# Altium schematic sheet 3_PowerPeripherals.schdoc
size 309 x 223 mm; Symbol: Artery_A4; Device: Artery_A4; Company: Artery Technology; Drawed: SD; Version: 1.3; Page Size: A4; @Project Name: AT-START-A403A V1.3; @Page Count: 5; @Update Date: 2023-11-22; @Create Date: 2022-12-01; @Schematic Name: AT_START_A403A; @Page No: 3; @Page Name: PowerPeripherals
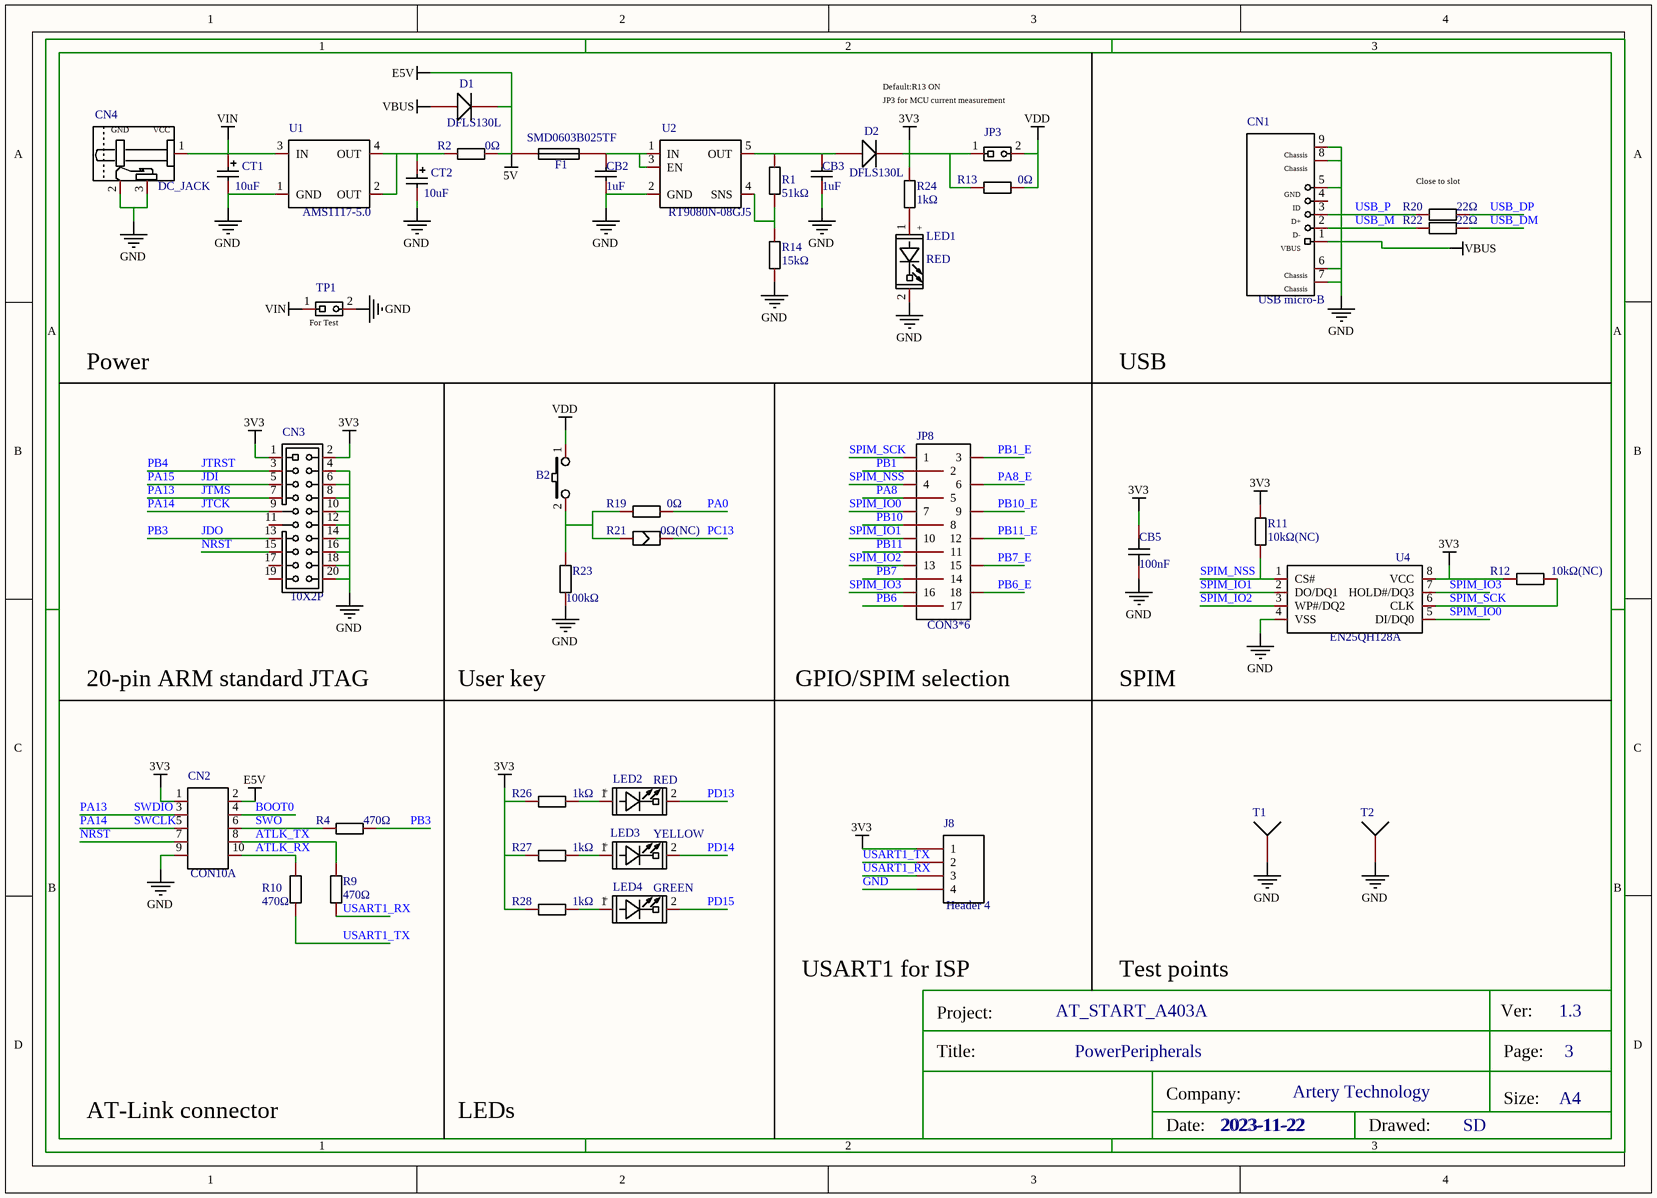
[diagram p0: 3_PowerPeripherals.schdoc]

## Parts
B2  PB,Blue,SMD_2P  [KEY_SOP_6*6]  (value not drawn)
CB2  value 1uF  [C0603]  (hidden comment: CL10A105KB8NNNC)
CB3  value 1uF  [C0603]  (hidden comment: CL10A105KB8NNNC)
CB5  value 100nF  [C0603]  (hidden comment: CC0603KRX7R9BB104)
CN1  USB micro-B  [USB_MIC_DIP]
CN2  CON10A  [HDR2X5]
CN3  10X2P  [JTAG_20]
CN4  DC_JACK  [DC10B]
CT1  value 10uF  [CAP-SMD_L3.5-W2.8-R-RD]  (hidden comment: CA45-B025K106T)
CT2  value 10uF  [CAP-SMD_L3.5-W2.8-R-RD]  (hidden comment: CA45-B025K106T)
D1  DFLS130L  [SOD-123]
D2  DFLS130L  [SOD-123]
F1  SMD0603B025TF  [R0603]
J8  Header 4  [HDR1X4]
JP3  1X2P_2.54M  [HDR1X2]  (value not drawn)
JP8  CON3*6  [HDR3X6]
LED1  RED  [LED0603]
LED2  RED  [LED0603]
LED3  YELLOW  [LED0603]
LED4  GREEN  [LED0603]
R1  value 51kΩ  [R0603]  (hidden comment: 0603WAF5102T5E)
R2  value 0Ω  [R0603]  (hidden comment: 0603WAF0000T5E)
R4  value 470Ω  [R0603]  (hidden comment: 0603WAF4700T5E)
R9  value 470Ω  [R0603]  (hidden comment: 0603WAF4700T5E)
R10  value 470Ω  [R0603]  (hidden comment: 0603WAF4700T5E)
R11  value 10kΩ(NC)  [R0603]  (hidden comment: 0603WAF1002T5E)
R12  value 10kΩ(NC)  [R0603]  (hidden comment: 0603WAF1002T5E)
R13  value 0Ω  [R0603]  (hidden comment: 0603WAF0000T5E)
R14  value 15kΩ  [R0603]  (hidden comment: 0603WAF1502T5E)
R19  value 0Ω  [R0603]  (hidden comment: 0603WAF0000T5E)
R20  value 22Ω  [R0603]  (hidden comment: 0603WAF220JT5E)
R21  value 0Ω(NC)  [SB-PAD]  (hidden comment: NC)
R22  value 22Ω  [R0603]  (hidden comment: 0603WAF220JT5E)
R23  value 100kΩ  [R0603]  (hidden comment: 0603WAF1003T5E)
R24  value 1kΩ  [R0603]  (hidden comment: 0603WAF1001T5E)
R26  value 1kΩ  [R0603]  (hidden comment: 0603WAF1001T5E)
R27  value 1kΩ  [R0603]  (hidden comment: 0603WAF1001T5E)
R28  value 1kΩ  [R0603]  (hidden comment: 0603WAF1001T5E)
T1  Socket  [TestPoint]  (value not drawn)
T2  Socket  [TestPoint]  (value not drawn)
TP1  1X2P_2.54M  [HDR1X2]  (value not drawn)
U1  AMS1117-5.0  [SOT223]
U2  RT9080N-08GJ5  [SOT-23-5]
U4  EN25QH128A  [SOIC8_208]

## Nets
3V3: CB5.2 CN2.1 CN3.1 CN3.2 D2.2(K) J8.1 JP3.1 R11.1 R12.1 R13.1 R24.2 R26.2 R27.2 R28.2 U4.8(VCC)
5V: CN2.2 D1.2(K) F1.1 R2.2  [also labelled E5V]
GND: CB2.1 CB3.1 CB5.1 CN1.5(GND) CN1.6 CN1.7 CN1.8 CN1.9 CN2.9 CN3.4 CN3.6 CN3.8 CN3.10 CN3.12 CN3.14 CN3.16 CN3.18 CN3.20 CN4.2 CN4.3 CT1.2 CT2.2 J8.4 LED1.2(CATHODE) R14.2 R23.2 T1.1 T2.1 TP1.2 U1.1(GND) U2.2(GND) U4.4(VSS)
VBUS: CN1.1(VBUS) D1.1(A)
VDD: B2.1 JP3.2 R13.2
VIN: CN4.1 CT1.1 TP1.1 U1.3(IN)
ATLK_RX: CN2.10 R10.2
ATLK_TX: CN2.8 R9.2
BOOT0: CN2.4
JDI: CN3.5  [also labelled PA15]
JDO: CN3.13 R4.1  [also labelled PB3]
JTCK: CN2.5 CN3.9  [also labelled PA14, SWCLK]
JTMS: CN2.3 CN3.7  [also labelled PA13, SWDIO]
JTRST: CN3.3  [also labelled PB4]
NRST: CN2.7 CN3.15
PA0: R19.1
PA8: JP8.5
PA8_E: JP8.6
PB1: JP8.2
PB1_E: JP8.3
PB6: JP8.17
PB6_E: JP8.18
PB7: JP8.14
PB7_E: JP8.15
PB10: JP8.8
PB10_E: JP8.9
PB11: JP8.11
PB11_E: JP8.12
PC13: R21.2
PD13: LED2.2(CATHODE)
PD14: LED3.2(CATHODE)
PD15: LED4.2(CATHODE)
SPIM_IO0: JP8.7 U4.5(DI/DQ0)
SPIM_IO1: JP8.10 U4.2(DO/DQ1)
SPIM_IO2: JP8.13 U4.3(WP#/DQ2)
SPIM_IO3: JP8.16 U4.7(HOLD#/DQ3)
SPIM_NSS: JP8.4 R11.2 U4.1(CS#)
SPIM_SCK: JP8.1 R12.2 U4.6(CLK)
SWO: CN2.6 R4.2
USART1_RX: J8.3 R9.1
USART1_TX: J8.2 R10.1
USB_DM: R22.1
USB_DP: R20.1
USB_M: CN1.2(D-) R22.2
USB_P: CN1.3(D+) R20.2
NetB2_2: B2.2 R19.2 R21.1 R23.1
NetCB2_2: CB2.2 F1.2 U2.1(IN) U2.3(EN)
NetCB3_2: CB3.2 D2.1(A) R1.1 U2.5(OUT)
NetCT2_1: CT2.1 R2.1 U1.2(OUT) U1.4(OUT)
NetLED1_1: LED1.1(ANODE) R24.1
NetLED2_1: LED2.1(ANODE) R26.1
NetLED3_1: LED3.1(ANODE) R27.1
NetLED4_1: LED4.1(ANODE) R28.1
NetR1_2: R1.2 R14.1 U2.4(SNS)

Not connected (* = marked no-connect by the designer): CN1 4(ID); CN3 11 17 19

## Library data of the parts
B2 = PB,Blue,SMD_2P: Symbol: Push_Bottom,Blue,SMD_2P; Add into BOM: yes
CB2 CB3 = CL10A105KB8NNNC: 容值:1uF;精度:±10%;额定电压:50V;材质(温度系数):X5R;; Manufacturer: SAMSUNG(三星); Add into BOM: yes; Tolerance: ±10%; Voltage Rated: 50V; Temperature Coefficient: X5R
CB5 = CC0603KRX7R9BB104: 容值:100nF;精度:±10%;额定电压:50V;材质(温度系数):X7R;; Manufacturer: YAGEO(国巨); Add into BOM: yes; Tolerance: ±10%; Voltage Rated: 50V; Temperature Coefficient: X7R
CN1 = USB micro-B: Symbol: USB_miniAB,SMD_0; Add into BOM: yes
CN2 = CON10A: Symbol: CON10A_0; Add into BOM: yes
CN3 = 10X2P: Symbol: 10x2P,Male,Housing,DIP_2.54; Add into BOM: yes
CN4 = DC_JACK: Symbol: DC12V_Power_JACK,2.0,DIP_3P; Add into BOM: yes
CT1 CT2 = CA45-B025K106T: 容值:10uF;精度:±10%;额定电压:25V;等效串联电阻:2.5Ω@100kHz;工作温度:-55℃~+125℃;; Manufacturer: 湘怡中元/湘江; Add into BOM: yes; Tolerance: ±10%; Rated Voltage: 25V
D1 D2 = DFLS130L: Default Diode; Add into BOM: yes
F1 = SMD0603B025TF: Fuse; Symbol: Fuse 1; Add into BOM: yes
J8 = Header 4: Header, 4-Pin; Add into BOM: yes
JP3 TP1 = 1X2P_2.54M: Symbol: 1X2P,Male,DIP_2.54; Origin Footprint 2: SIP_2P; Add into BOM: yes; Origin Footprint 1: HDR1X2 - SOP
JP8 = CON3*6: Add into BOM: yes
LED1 LED2 = RED: Symbol: RED,SMD0603; Add into BOM: yes
LED3 = YELLOW: Symbol: YELLOW,SMD0603; Add into BOM: yes
LED4 = GREEN: Symbol: GREEN,SMD0603; Add into BOM: yes
R1 = 0603WAF5102T5E: 电阻类型:厚膜电阻;阻值:51kΩ;精度:±1%;功率:100mW;温度系数:±100ppm/℃;最大工作电压:75V;工作温度范围:-55℃~+155℃;; Manufacturer: UNI-ROYAL(厚声); Add into BOM: yes; Tolerance: ±1%; Power(Watts): 100mW; Overload Voltage (Max): 75V
R2 R13 R19 = 0603WAF0000T5E: 电阻类型:厚膜电阻;阻值:0Ω;精度:±1%;功率:100mW;最大工作电压:75V;工作温度范围:-55℃~+155℃;; Manufacturer: UNI-ROYAL(厚声); Add into BOM: yes; Tolerance: ±1%; Power(Watts): 100mW; Overload Voltage (Max): 75V
R4 R9 R10 = 0603WAF4700T5E: 电阻类型:厚膜电阻;阻值:470Ω;精度:±1%;功率:100mW;温度系数:±100ppm/℃;最大工作电压:75V;工作温度范围:-55℃~+155℃;; Manufacturer: UNI-ROYAL(厚声); Add into BOM: yes; Tolerance: ±1%; Power(Watts): 100mW; Overload Voltage (Max): 75V
R11 R12 = 0603WAF1002T5E: 电阻类型:厚膜电阻;阻值:10kΩ;精度:±1%;功率:100mW;温度系数:±100ppm/℃;最大工作电压:75V;工作温度范围:-55℃~+155℃;; Manufacturer: UNI-ROYAL(厚声); Add into BOM: yes; Tolerance: ±1%; Power(Watts): 100mW; Overload Voltage (Max): 75V
R14 = 0603WAF1502T5E: 电阻类型:厚膜电阻;阻值:15kΩ;精度:±1%;功率:100mW;温度系数:±100ppm/℃;最大工作电压:75V;工作温度范围:-55℃~+155℃;; Manufacturer: UNI-ROYAL(厚声); Add into BOM: yes; Tolerance: ±1%; Power(Watts): 100mW; Overload Voltage (Max): 75V
R20 R22 = 0603WAF220JT5E: 电阻类型:厚膜电阻;阻值:22Ω;精度:±1%;功率:100mW;温度系数:±100ppm/℃;最大工作电压:75V;工作温度范围:-55℃~+155℃;; Manufacturer: UNI-ROYAL(厚声); Add into BOM: yes; Tolerance: ±1%; Power(Watts): 100mW; Overload Voltage (Max): 75V
R21 = NC_SB-PAD: Convert to PCB: yes
R23 = 0603WAF1003T5E: 电阻类型:厚膜电阻;阻值:100kΩ;精度:±1%;功率:100mW;温度系数:±100ppm/℃;最大工作电压:75V;工作温度范围:-55℃~+155℃;; Manufacturer: UNI-ROYAL(厚声); Add into BOM: yes; Tolerance: ±1%; Power(Watts): 100mW; Overload Voltage (Max): 75V
R24 R26-R28 = 0603WAF1001T5E: 电阻类型:厚膜电阻;阻值:1kΩ;精度:±1%;功率:100mW;温度系数:±100ppm/℃;最大工作电压:75V;工作温度范围:-55℃~+155℃;; Manufacturer: UNI-ROYAL(厚声); Add into BOM: yes; Tolerance: ±1%; Power(Watts): 100mW; Overload Voltage (Max): 75V
T1 T2 = Socket: Add into BOM: yes
U1 = AMS1117-5.0: Symbol: AMS1117-3.3; Add into BOM: yes
U2 = RT9080N-08GJ5: Add into BOM: yes
U4 = EN25QH128A: Symbol: W25Q128FVSIQ,SOIC8_1; Add into BOM: yes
